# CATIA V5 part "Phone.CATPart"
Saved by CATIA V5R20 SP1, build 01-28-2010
Part number: Part1
Bounding box of the stored display mesh (mm): x -100 to 99.999, y -30 to 30, z -8.053 to 30
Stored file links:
  J:\hosseini\Phone.CATPart
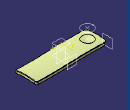
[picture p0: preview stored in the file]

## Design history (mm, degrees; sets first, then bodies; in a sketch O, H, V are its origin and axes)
Body1 (main body)
  Plane1: type Offset, RefPlane zx-plane, Offset 30
  Sketch1 on Plane1, origin (0, 30, 0), H (-1, 0, 0), V (0, 0, 1)
    spline S1 through (100, 0) (27.5239, 1) (-68.4765, -1) (-100, 0)
    point P1 (100, 0)
    point P2 (-100, 0)
    point P3 (27.5239, 1)
    point P4 (-68.4765, -1)
    distance P1 P2 H = 200
    distance P3 H = 1
    distance P4 H = 1
    coincidence: P1 H
    symmetry: P1 P2 V
  Symmetry1: Reference zx-plane, ToTransfor Sketch1
  Plane2: type OffsetPt, RefPlane yz-plane, RefPoint Sketch1.P1
  Sketch2 on Plane2, origin (-100, 0, 0), H (0, 1, 0), V (0, 0, 1)
    arc A1 centre (0, -157.1623) radius 160 from (30, 0) to (-30, 0) ccw
    point P2 (30, 0)
    point P3 (-30, 0)
    reference projected point E1 (30, 0) from Sketch1.P1
    reference projected point E2 (-30, 0) from vertex of Symmetry1
    radius A1 = 160
    coincidence: P2 E1, E2 P3
  Sweep1: type Unspec, Profile Sketch2, Guide (Sketch1; Symmetry1)
  Boundary1: Boundary edge of Sweep1
  Extrude1: Element1 Boundary1, Lim1 4, Lim2 7, Direction (0, 0, 1)
  Fillet1: radius 5, on edge [face of Extrude1 | face of Extrude1] (x2)
  Fillet2: radius 8, on edge [face of Extrude1 | face of Extrude1] (x2)
  Fillet3: type BiTangent, Element1 Fillet2, Element2 Sweep1, Radius 1
  Plane3: type Offset, RefPlane xy-plane, Offset 30
  Sketch3 on Plane3, origin (0, 0, 30), H (1, 0, 0), V (0, 1, 0)
    circle A1 centre (-73.9458, 0) radius 15.4872
    point P1 (-73.9458, 0)
    coincidence: P1 H
  Project1: ToProject Sketch3, Support Fillet3, Direction (0, 0, 1)
  Point1: type Center, Curve Sketch3
  Project2: ToProject Point1, Support Fillet3
  GSOBump1: BodyToBump Fillet3, LimitCurve Project1, DeformationCenter Project2, DeformationDirection Z axis, DeformationDistance -2, CenterTension 0.005
  Fillet4: radius 0.5, on edge [face of Sweep1 | face of Sweep1]
  Sketch4 on Plane3, origin (0, 0, 30), H (1, 0, 0), V (0, 1, 0)
    circle A1 centre (-4.9011, 0) radius 11.3208
    point P1 (-4.9011, 0)
    coincidence: P1 H
  Project3: ToProject Sketch4, Support Fillet4, Direction (0, 0, 1)
  Split1: ToCut Fillet4, Cutting Project3
  Translate1: ToTransfor Project3, Direction (0, 0, 1), Length -2
  3DCurveOffset1: Curve Translate1, Direction (0, 0, 1), Offset -2, CornerRadius 1, CornerTension 0.5
  Loft1: Sections (Project3; 3DCurveOffset1)
  Sketch5 on Plane3, origin (0, 0, 30), H (1, 0, 0), V (0, 1, 0)
    point P1 (-41.9036, 0)
    line L1 (-29.232, 25.3745) -> (-29.232, -25.3745)
    line L2 (-29.232, -25.3745) -> (-54.5751, -25.3745)
    line L3 (-54.5751, -25.3745) -> (-54.5751, 25.3745)
    line L4 (-54.5751, 25.3745) -> (-29.232, 25.3745)
    coincidence: P1 H
    vertical: L1 V, L3 V
    horizontal: L2 H, L4 H
    equidistance: L1 L3 P1, L2 L4 P1
  Project4: ToProject Sketch5, Support Split1, Direction (0, 0, 1)
  Split2: ToCut Split1, Cutting Project4
  Extrude2: Element1 Project4, Lim1 0, Lim2 1, Direction (0, 0, 1)
  Join1: Elements (Extrude2; Split2; Loft1)
  Fillet5: radius 2, on edge [face of Extrude2 | face of Extrude2] (x4)
  Fillet6: radius 0.1, on edge [face of Extrude2 | face of Sweep1]
  Fillet7: radius 0.1, on edge [face of Sweep1 | face of Loft1]
  Sketch6 on Plane3, origin (0, 0, 30), H (1, 0, 0), V (0, 1, 0)
    point P1 (-22.3866, 16.8942)
    line L1 (-19.7089, 21.2444) -> (-19.7089, 12.5441)
    line L2 (-20.7089, 11.5441) -> (-24.0643, 11.5441)
    line L3 (-25.0643, 12.5441) -> (-25.0643, 21.2444)
    line L4 (-24.0643, 22.2444) -> (-20.7089, 22.2444)
    arc A1 centre (-20.7089, 21.2444) radius 1 from (-19.7089, 21.2444) to (-20.7089, 22.2444) ccw
    arc A2 centre (-24.0643, 21.2444) radius 1 from (-25.0643, 21.2444) to (-24.0643, 22.2444) cw
    arc A3 centre (-24.0643, 12.5441) radius 1 from (-24.0643, 11.5441) to (-25.0643, 12.5441) cw
    arc A4 centre (-20.7089, 12.5441) radius 1 from (-19.7089, 12.5441) to (-20.7089, 11.5441) cw
    point P14 (-19.7089, 16.8942)
    point P15 (-22.3866, 22.2444)
    point P16 (-25.0643, 16.8942)
    point P17 (-22.3866, 11.5441)
    radius A1 = 1
    radius A2 = 1
    radius A4 = 1
    radius A3 = 1
    vertical: L1 V, L3 V
    horizontal: L2 H, L4 H
    equidistance: L1 L3 P1, L2 L4 P1
    tangency: A1 L1, A1 L4, A2 L3, A2 L4, A3 L2, A3 L3, A4 L1, A4 L2
    midpoint: P14 L1, P15 L4, P16 L3, P17 L2
  Project5: ToProject Sketch6, Support Fillet7, Direction (0, 0, 1)
  Translate2: ToTransfor Project5, Direction (0, 0, 1), Length -1.5
  3DCurveOffset2: Curve Translate2, Direction (0, 0, 1), Offset 1.1, CornerRadius 0.5, CornerTension 0.5
  Project6: ToProject Sketch6.P14, Support Fillet7, Direction (0, 0, 1)
  Project7: ToProject Sketch6.P17, Support Fillet7, Direction (0, 0, 1)
  Project8: ToProject Sketch6.P16, Support Fillet7, Direction (0, 0, 1)
  Project9: ToProject Sketch6.P15, Support Fillet7, Direction (0, 0, 1)
  Plane4: type OffsetPt, RefPlane zx-plane, RefPoint Project6
  Plane5: type OffsetPt, RefPlane yz-plane, RefPoint Project9
  Intersect1: ToIntersect1 Plane4, ToIntersect2 3DCurveOffset2
  Near1: MultiElement Intersect1, ReferenceElement Project6
  Intersect2: ToIntersect1 Plane5, ToIntersect2 3DCurveOffset2
  Near2: MultiElement Intersect2, ReferenceElement Project9
  Sketch7 on Plane4, origin (0, 16.8942, 0), H (-1, 0, 0), V (0, 0, 1)
    arc A1 centre (21.6867, 3.0651) radius 2 from (19.7089, 2.7681) to (20.8089, 1.2681) ccw
    point P2 (19.7089, 2.7681)
    point P3 (20.8089, 1.2681)
    reference projected point E1 (20.8089, 1.2681) from Near1
    reference projected point E2 (19.7089, 2.7681) from Project6
    radius A1 = 2
    coincidence: E1 P3, E2 P2
  Sketch8 on Plane5, origin (-22.3866, 0, 0), H (0, 1, 0), V (0, 0, 1)
    arc A1 centre (20.2666, 2.47) radius 2 from (22.2444, 2.1729) to (21.1444, 0.6729) cw
    point P2 (22.2444, 2.1729)
    point P3 (21.1444, 0.6729)
    reference projected point E1 (21.1444, 0.6729) from Near2
    reference projected point E2 (22.2444, 2.1729) from Project9
    radius A1 = 2
    coincidence: E1 P3, P2 E2
  Intersect3: ToIntersect1 Plane4, ToIntersect2 3DCurveOffset2
  Near3: MultiElement Intersect3, ReferenceElement Project8
  Intersect4: ToIntersect1 Plane5, ToIntersect2 3DCurveOffset2
  Near4: MultiElement Intersect4, ReferenceElement Project7
  Sketch9 on Plane4, origin (0, 16.8942, 0), H (-1, 0, 0), V (0, 0, 1)
    arc A1 centre (23.0865, 3.1879) radius 2 from (23.9643, 1.3908) to (25.0643, 2.8908) ccw
    point P2 (23.9643, 1.3908)
    point P3 (25.0643, 2.8908)
    reference projected point E1 (23.9643, 1.3908) from Near3
    reference projected point E2 (25.0643, 2.8908) from Project8
    radius A1 = 2
    coincidence: E1 P2, P3 E2
  Sketch10 on Plane5, origin (-22.3866, 0, 0), H (0, 1, 0), V (0, 0, 1)
    arc A1 centre (13.5219, 3.6056) radius 2 from (11.5441, 3.3086) to (12.6441, 1.8086) ccw
    point P2 (11.5441, 3.3086)
    point P3 (12.6441, 1.8086)
    reference projected point E1 (12.6441, 1.8086) from Near4
    reference projected point E2 (11.5441, 3.3086) from Project7
    radius A1 = 2
    coincidence: P3 E1, E2 P2
  Split3: ToCut Fillet7, Cutting Project5
  Loft2: Sections (Project5; 3DCurveOffset2), Guides (Sketch7; Sketch9), SectionCouplingPoints ({coupling CouplingPoints (vertex [face of Project5 | face of Project5]; vertex [face of 3DCurveOffset2 | face of 3DCurveOffset2])}; {coupling CouplingPoints (vertex [face of Project5 | face of Project5]; vertex [face of 3DCurveOffset2 | face of 3DCurveOffset2])}; {coupling CouplingPoints (vertex [face of Project5 | face of Project5]; vertex [face of 3DCurveOffset2 | face of 3DCurveOffset2])}; {coupling CouplingPoints (vertex [face of Project5 | face of Project5]; vertex [face of 3DCurveOffset2 | face of 3DCurveOffset2])}; {coupling CouplingPoints (vertex [face of Project5 | face of Project5]; vertex [face of 3DCurveOffset2 | face of 3DCurveOffset2])}; {coupling CouplingPoints (vertex [face of Project5 | face of Project5]; vertex [face of 3DCurveOffset2 | face of 3DCurveOffset2])}; {coupling CouplingPoints (vertex [face of Project5 | face of Project5]; vertex [face of 3DCurveOffset2 | face of 3DCurveOffset2])})
  Boundary2: Boundary edge of Split3
  Extrapol1: ToExtrapol Boundary2, Support Loft2, Length 1
  Point2: type Center, Curve Sketch2
  Line1: type PtDir, RefPoint Point2, Direction (1, 0, 0), Start 0, End 77
  Rotate1: ToTransfor Extrapol1, Axis Line1, Angle 6.087
  Rotate2: ToTransfor Extrapol1, Axis Line1, Angle 12.174
  Fillet8: type BiTangent, Element1 Split3, Element2 Extrapol1, Radius 0.1
  Fillet9: type BiTangent, Element1 Fillet8, Element2 Rotate1, Radius 0.1
  Fillet10: type BiTangent, Element1 Rotate2, Element2 Fillet9, Radius 0.1
  Sketch11 on Plane3, origin (0, 0, 30), H (1, 0, 0), V (0, 1, 0)
    point P1 (-5.9011, 24.9666)
    line L1 (-6.9011, 24.9666) -> (-15.7089, 24.9666)
    line L2 (-16.7089, 23.9666) -> (-16.7089, 13.1417)
    point P2 (-16.7089, 12.1417)
    line L3 (-15.7089, 12.1417) -> (-14.3357, 12.1417)
    point P3 (-13.7089, 12.1417)
    arc A1 centre (-4.9011, 0) radius 15 from (-13.2257, 12.478) to (-6.7761, 14.8824) cw
    point P4 (-4.9011, 0)
    point P5 (-5.9011, 14.9666)
    line L4 (-5.9011, 15.8745) -> (-5.9011, 23.9666)
    reference projected circle E1 centre (-4.9011, 0) radius 11.3208 from edge of Translate1
    reference projected line E2 (-19.7089, 12.5441) -> (-19.7089, 21.2444) from edge of Split3
    arc A2 centre (-6.9011, 23.9666) radius 1 from (-5.9011, 23.9666) to (-6.9011, 24.9666) ccw
    arc A3 centre (-15.7089, 23.9666) radius 1 from (-15.7089, 24.9666) to (-16.7089, 23.9666) ccw
    arc A4 centre (-6.9011, 15.8745) radius 1 from (-6.7761, 14.8824) to (-5.9011, 15.8745) ccw
    arc A5 centre (-14.3357, 14.1417) radius 2 from (-13.2257, 12.478) to (-14.3357, 12.1417) cw
    arc A6 centre (-15.7089, 13.1417) radius 1 from (-16.7089, 13.1417) to (-15.7089, 12.1417) ccw
    radius A1 = 15
    distance L4 P4 = 1
    distance E2 L2 = 3
    distance P5 P1 = 10
    radius A2 = 1
    radius A3 = 1
    radius A4 = 1
    distance P2 P3 = 3
    radius A5 = 2
    radius A6 = 1
    horizontal: L1 H, L3 H
    vertical: L2 V, L4 V
    concentricity: A1 E1
    coincidence: L4 P1, L1 P1, A1 P5, L4 P5, A1 P3, L3 P3, L2 P2, L3 P2
    tangency: A2 L4, A2 L1, A3 L1, A3 L2, A4 L4, A4 A1, A5 L3, A5 A1, A6 L2, A6 L3
  Project10: ToProject Sketch11, Support Fillet10, Direction (0, 0, 1)
  Translate3: ToTransfor Project10, Direction (0, 0, 1), Length -1.5
  3DCurveOffset3: Curve Translate3, Direction (0, 0, 1), Offset 1.1, CornerRadius 0.5, CornerTension 0.5
  Loft3: Sections (Project10; 3DCurveOffset3), SectionCouplingPoints ({coupling CouplingPoints (vertex [face of Project10 | face of Project10]; vertex [face of 3DCurveOffset3 | face of 3DCurveOffset3])}; {coupling CouplingPoints (vertex [face of Project10 | face of Project10]; vertex [face of 3DCurveOffset3 | face of 3DCurveOffset3])}; {coupling CouplingPoints (vertex [face of Project10 | face of Project10]; vertex [face of 3DCurveOffset3 | face of 3DCurveOffset3])}; {coupling CouplingPoints (vertex [face of Project10 | face of Project10]; vertex [face of 3DCurveOffset3 | face of 3DCurveOffset3])}; {coupling CouplingPoints (vertex [face of Project10 | face of Project10]; vertex [face of 3DCurveOffset3 | face of 3DCurveOffset3])}; {coupling CouplingPoints (vertex [face of Project10 | face of Project10]; vertex [face of 3DCurveOffset3 | face of 3DCurveOffset3])}; {coupling CouplingPoints (vertex [face of Project10 | face of Project10]; vertex [face of 3DCurveOffset3 | face of 3DCurveOffset3])}; {coupling CouplingPoints (vertex [face of Project10 | face of Project10]; vertex [face of 3DCurveOffset3 | face of 3DCurveOffset3])}; {coupling CouplingPoints (vertex [face of Project10 | face of Project10]; vertex [face of 3DCurveOffset3 | face of 3DCurveOffset3])}; {coupling CouplingPoints (vertex [face of Project10 | face of Project10]; vertex [face of 3DCurveOffset3 | face of 3DCurveOffset3])})
  Split4: ToCut Fillet10, Cutting Project10
  Boundary3: Boundary edge of Split4
  Extrapol2: ToExtrapol Boundary3, Support Loft3, Length 1.5
  Symmetry2: Reference zx-plane, ToTransfor Extrapol2
  Point3: type Center, Curve Sketch4
  Plane6: type OffsetPt, RefPlane yz-plane, RefPoint Point3
  Symmetry3: Reference Plane6, ToTransfor Sketch11
  Project11: ToProject Symmetry3, Support Split4, Direction (0, 0, 1)
  Split5: ToCut Split4, Cutting Project11
  Intersect5: ToIntersect1 Symmetry2, ToIntersect2 Split5
  Split6: ToCut Split5, Cutting Intersect5
  Boundary4: Boundary edge of Split5
  Translate4: ToTransfor Boundary4, Direction (0, 0, 1), Length -1.5
  3DCurveOffset4: Curve Translate4, Direction (0, 0, 1), Offset 1.1, CornerRadius 0.5, CornerTension 0.5
  Loft4: Sections (Project11; 3DCurveOffset4), SectionCouplingPoints ({coupling CouplingPoints (vertex [face of Project11 | face of Project11]; vertex [face of 3DCurveOffset4 | face of 3DCurveOffset4])}; {coupling CouplingPoints (vertex [face of Project11 | face of Project11]; vertex [face of 3DCurveOffset4 | face of 3DCurveOffset4])}; {coupling CouplingPoints (vertex [face of Project11 | face of Project11]; vertex [face of 3DCurveOffset4 | face of 3DCurveOffset4])}; {coupling CouplingPoints (vertex [face of Project11 | face of Project11]; vertex [face of 3DCurveOffset4 | face of 3DCurveOffset4])}; {coupling CouplingPoints (vertex [face of Project11 | face of Project11]; vertex [face of 3DCurveOffset4 | face of 3DCurveOffset4])}; {coupling CouplingPoints (vertex [face of Project11 | face of Project11]; vertex [face of 3DCurveOffset4 | face of 3DCurveOffset4])}; {coupling CouplingPoints (vertex [face of Project11 | face of Project11]; vertex [face of 3DCurveOffset4 | face of 3DCurveOffset4])}; {coupling CouplingPoints (vertex [face of Project11 | face of Project11]; vertex [face of 3DCurveOffset4 | face of 3DCurveOffset4])}; {coupling CouplingPoints (vertex [face of Project11 | face of Project11]; vertex [face of 3DCurveOffset4 | face of 3DCurveOffset4])})
  Extrapol3: ToExtrapol Boundary4, Support Loft4, Length 1.5
  Symmetry4: Reference zx-plane, ToTransfor Extrapol3
  Intersect6: ToIntersect1 Split6, ToIntersect2 Symmetry4
  Split7: ToCut Split6, Cutting Intersect6
  Fillet11: type BiTangent, Element1 Extrapol3, Element2 Split7, Radius 0.1
  Fillet12: type BiTangent, Element1 Fillet11, Element2 Symmetry4, Radius 0.1
  Fillet13: type BiTangent, Element1 Fillet12, Element2 Extrapol2, Radius 0.1
  Fillet14: type BiTangent, Element1 Fillet13, Element2 Symmetry2, Radius 0.1
  Sketch12 on Plane3, origin (0, 0, 30), H (1, 0, 0), V (0, 1, 0)
    circle A1 centre (-73.9458, 0) radius 1
    point P1 (-73.9458, 0)
    reference projected circle E1 centre (-73.9458, 0) radius 15.4872 from edge of Project1
    radius A1 = 1
    coincidence: P1 H
    concentricity: A1 E1
  Sketch13 on Plane3, origin (0, 0, 30), H (1, 0, 0), V (0, 1, 0)
    point P1 (21.958, 0)
    line L1 (25.958, 6) -> (25.958, -6)
    line L2 (25.958, -6) -> (17.958, -6)
    line L3 (17.958, -6) -> (17.958, 6)
    line L4 (17.958, 6) -> (25.958, 6)
    length L3 = 12
    length L4 = 8
    coincidence: P1 H
    vertical: L1 V, L3 V
    horizontal: L2 H, L4 H
    equidistance: L1 L3 P1, L2 L4 P1
  Project12: ToProject Sketch13, Support Fillet14, Direction (0, 0, 1)
  Extrude3: Element1 Project12, Lim1 2, Lim2 1, Direction (0, 0, 1)
  Rotate3: ToTransfor Extrude3, Axis Line1, Angle 6
  Rotate4: ToTransfor Extrude3, Axis Line1, Angle -6
  Fillet15: type BiTangent, Element1 Fillet14, Element2 Rotate4, Radius 0.1
  Fillet16: type BiTangent, Element1 Extrude3, Element2 Fillet15, Radius 0.1
  Fillet17: type BiTangent, Element1 Rotate3, Element2 Fillet16, Radius 0.1
Current feature: Fillet4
